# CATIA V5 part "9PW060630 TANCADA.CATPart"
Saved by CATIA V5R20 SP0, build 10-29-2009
Part number: 9PW060630 TANCADA
Revision: ANY
Definition: UNKNOWN
Nomenclature: 9PW060630 TANCADA
Source: Unknown
Bounding box of the stored display mesh (mm): x -175 to 0, y -6.5 to 3.5, z -3.1 to 3.1
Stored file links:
  C:\Users\Utente\Desktop\IO LAVORO\3D X SITO CF\CUMSA\3D files PW\pw060630\pw060630_injection\9PW060630 TANCADA.CATPart
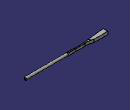
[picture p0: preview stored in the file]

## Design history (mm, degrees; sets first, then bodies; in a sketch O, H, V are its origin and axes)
Body1 "Chaflán1" (main body)
  Solid1: solid without history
